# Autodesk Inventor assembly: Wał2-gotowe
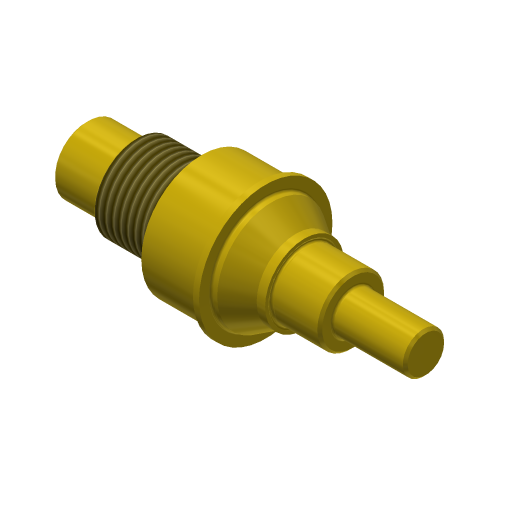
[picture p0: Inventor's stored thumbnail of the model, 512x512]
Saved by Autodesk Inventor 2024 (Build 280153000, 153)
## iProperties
Company: ATC
ClientObjectVersion: 1
Created: 2023-03
Part Number: Wał2-gotowe
Document SubType Name: Assembly
Designer: Andrzej Jaskulski
Stock Number: Wał2-gotowe
Checked By: A.J.
Engr Approved By: Andrzej Jaskulski
Mfg Approved By: Andrzej Jaskulski
Authority: A.J.
Title: A.J.: Kurs R2024-MEP
Author: Andrzej Jaskulski
Revision Number: 1/24
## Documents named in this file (2)
- C:\Users\AndJas\Documents\R2024-MEP\Obszar roboczy\PZ\GOTOWE\Wał2-gotowe.iam
- C:\Users\AndJas\Documents\R2024-MEP\Obszar roboczy\PZ\GOTOWE\Wał2-gotowe.ipt
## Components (1 placed, 1 different names)
1. Wał:1
